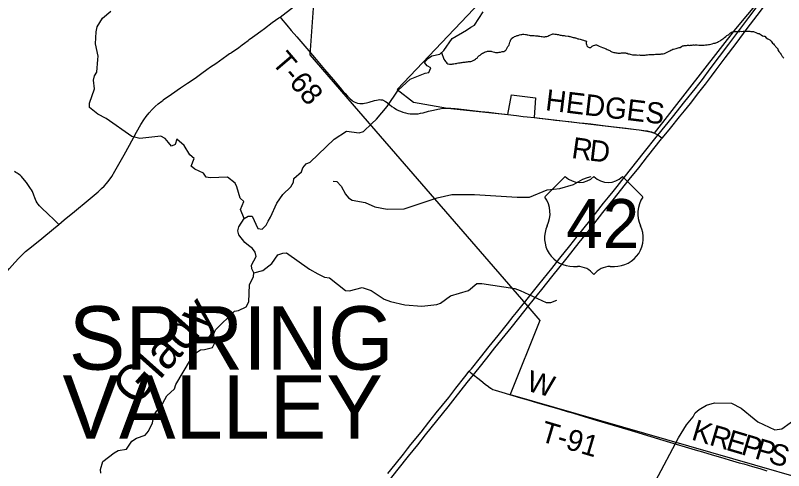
# Model space of a CAD drawing. Extents: x -19.5 to 44.1, y 0 to 22.
# Drawn here: x -15.579 to -13.513, y 18.108 to 19.332 of the extents above; entities that cross this region are included whole.
import ezdxf

# ---------------------------------------------------------------- set-up
doc = ezdxf.new("R2010")
doc.units = 0
for name, color, linetype in [('GM_X_Corporation', 7, 'Continuous'), ('GM_X_County_Road', 7, 'Continuous'), ('GM_X_Minor_River', 7, 'Continuous'), ('GM_X_Minor_River_Text', 7, 'Continuous'), ('GM_X_Township', 7, 'Continuous'), ('GM_X_Township_Road', 7, 'Continuous'), ('GM_X_Township_Road_Text', 7, 'Continuous'), ('GM_X_Township_Text', 7, 'Continuous'), ('GM_X_US_Location', 7, 'Continuous'), ('GM_X_US_Route', 7, 'Continuous'), ('GM_X_US_Shield', 7, 'Continuous')]:
    doc.layers.add(name, color=color, linetype=linetype)

msp = doc.modelspace()

# ---------------------------------------------------------------- linework, layer by layer
at = {"layer": 'GM_X_Corporation'}
msp.add_lwpolyline([(-14.0734, 19.638), (-14.5525, 19.1324), (-14.5085, 19.0988), (-14.4176, 19.0831), (-14.2547, 19.0654), (-14.2455, 19.1182), (-14.1803, 19.1107), (-14.1842, 19.0573), (-13.9021, 19.0241), (-13.8716, 19.0193), (-13.8606, 19.0152), (-13.6422, 19.296), (-13.5447, 19.4122)], dxfattribs=at)
at = {"layer": 'GM_X_County_Road'}
for points in [[(-14.8675, 19.3277), (-14.8315, 19.3546)], [(-15.4629, 18.7701), (-15.4479, 18.7823), (-15.4207, 18.805), (-15.384, 18.8357), (-15.3571, 18.8578), (-15.3474, 18.8665), (-15.3404, 18.8734), (-15.3342, 18.8803), (-15.3273, 18.889), (-15.3203, 18.8992), (-15.3119, 18.9129), (-15.2975, 18.9383), (-15.287, 18.9573), (-15.2726, 18.9834), (-15.2534, 19.0182), (-15.2418, 19.0388), (-15.2343, 19.051), (-15.2279, 19.0602), (-15.2197, 19.0704), (-15.2117, 19.0792), (-15.2033, 19.0875), (-15.1952, 19.0944), (-15.1859, 19.1016), (-15.183, 19.1037), (-15.1816, 19.1047), (-15.1592, 19.1203), (-15.1353, 19.137), (-15.1169, 19.1497), (-15.0962, 19.1635), (-15.0775, 19.1768), (-15.0644, 19.1863), (-15.0543, 19.1934), (-15.0406, 19.2029), (-15.0103, 19.2246), (-15.0032, 19.2295), (-15.0011, 19.2308), (-14.9986, 19.2326), (-14.9945, 19.2353), (-14.9903, 19.2379), (-14.9787, 19.2461), (-14.9691, 19.253), (-14.9636, 19.257), (-14.9535, 19.2645), (-14.9502, 19.2669), (-14.9418, 19.2731), (-14.9353, 19.278), (-14.9193, 19.2896), (-14.9094, 19.297), (-14.8884, 19.3126), (-14.8707, 19.3252), (-14.8675, 19.3277)], [(-15.7973, 18.403), (-15.7928, 18.4083), (-15.7779, 18.4266), (-15.7621, 18.4466), (-15.7433, 18.4706), (-15.7194, 18.5016), (-15.7037, 18.5216), (-15.692, 18.5362), (-15.6732, 18.5593), (-15.6533, 18.5832), (-15.6076, 18.6373), (-15.5955, 18.6515), (-15.5813, 18.6679), (-15.5704, 18.6799), (-15.5615, 18.6887), (-15.5522, 18.697), (-15.5364, 18.71), (-15.5083, 18.7326), (-15.4767, 18.7587), (-15.4629, 18.7701)]]:
    msp.add_lwpolyline(points, dxfattribs=at)
at = {"layer": 'GM_X_Minor_River'}
for points in [[(-14.9644, 18.7865), (-14.9739, 18.8102), (-14.9651, 18.832), (-14.9749, 18.8406), (-14.9834, 18.8715), (-14.9886, 18.8811), (-15.0088, 18.8973), (-15.0552, 18.8951), (-15.0661, 18.8976), (-15.0739, 18.908), (-15.0969, 18.9186), (-15.107, 18.9267), (-15.0987, 18.9475), (-15.1099, 18.9576), (-15.1258, 18.9821), (-15.1449, 18.9995), (-15.1493, 18.9848), (-15.1597, 18.9804), (-15.1675, 18.9901), (-15.1768, 19.0012), (-15.1881, 19.0071), (-15.2447, 19.0009), (-15.2663, 19.0062), (-15.3349, 19.0552), (-15.3579, 19.0666), (-15.3804, 19.0848), (-15.3802, 19.0959), (-15.367, 19.1347), (-15.3692, 19.1583), (-15.3668, 19.1697), (-15.3605, 19.1794), (-15.3577, 19.2132), (-15.3571, 19.2227), (-15.3638, 19.2558), (-15.3625, 19.2877), (-15.3596, 19.3013), (-15.3448, 19.3242), (-15.3228, 19.3432)], [(-14.7219, 18.9991), (-14.6893, 19.0206), (-14.6552, 19.0162), (-14.6434, 19.0198), (-14.621, 19.0415), (-14.6079, 19.053), (-14.5792, 19.0871), (-14.5503, 19.131), (-14.5175, 19.1608), (-14.477, 19.1768), (-14.4671, 19.1782), (-14.462, 19.191), (-14.4721, 19.1961), (-14.4792, 19.2057), (-14.4714, 19.2155), (-14.4592, 19.2229), (-14.4378, 19.2274), (-14.427, 19.2379), (-14.4044, 19.2701), (-14.3665, 19.2927), (-14.3546, 19.3001), (-14.345, 19.306), (-14.3212, 19.342)], [(-14.4331, 19.2322), (-14.4271, 19.2144), (-14.4245, 19.2109), (-14.4222, 19.2079), (-14.4211, 19.206), (-14.4188, 19.2033), (-14.4166, 19.2021), (-14.4116, 19.201), (-14.4094, 19.2013), (-14.4075, 19.2013), (-14.4048, 19.2013), (-14.4029, 19.2016), (-14.3999, 19.202), (-14.3968, 19.2027), (-14.3931, 19.2031), (-14.3912, 19.2034), (-14.3874, 19.2042), (-14.3847, 19.2045), (-14.3828, 19.2045), (-14.3801, 19.2052), (-14.3775, 19.2056), (-14.3748, 19.206), (-14.3726, 19.2063), (-14.3695, 19.2067), (-14.3672, 19.207), (-14.365, 19.207), (-14.3631, 19.2074), (-14.3608, 19.2077), (-14.3585, 19.2077), (-14.3566, 19.2081), (-14.3547, 19.2084), (-14.3521, 19.2088), (-14.3486, 19.2107), (-14.3464, 19.2118), (-14.3445, 19.2129), (-14.3422, 19.2148), (-14.3399, 19.2163), (-14.3372, 19.2174), (-14.3357, 19.2204), (-14.3326, 19.2234), (-14.3296, 19.2253), (-14.328, 19.2272), (-14.3254, 19.2291), (-14.3227, 19.2306), (-14.3208, 19.2313), (-14.3178, 19.2332), (-14.3151, 19.2339), (-14.3117, 19.235), (-14.3098, 19.2358), (-14.3079, 19.2357), (-14.306, 19.2357), (-14.303, 19.2357), (-14.2999, 19.2357), (-14.2977, 19.2353), (-14.2946, 19.2345), (-14.2912, 19.2333), (-14.2882, 19.2325), (-14.2848, 19.2321), (-14.2829, 19.2321), (-14.2806, 19.2325), (-14.278, 19.2328), (-14.2749, 19.2336), (-14.27, 19.2347), (-14.2673, 19.235), (-14.2654, 19.2354), (-14.2635, 19.2369), (-14.2616, 19.238), (-14.2597, 19.2391), (-14.257, 19.2444), (-14.2547, 19.2482), (-14.2524, 19.2512), (-14.2513, 19.2531), (-14.2509, 19.2561), (-14.2493, 19.2599), (-14.2482, 19.2633), (-14.2474, 19.2652), (-14.2459, 19.2671), (-14.2447, 19.2697), (-14.2413, 19.2727), (-14.2386, 19.2738), (-14.2367, 19.2753), (-14.2336, 19.2765), (-14.2298, 19.2779), (-14.2268, 19.2783), (-14.2234, 19.2798), (-14.22, 19.2805), (-14.2173, 19.2809), (-14.2147, 19.2812), (-14.2116, 19.2812), (-14.2078, 19.2804), (-14.2056, 19.2804), (-14.2033, 19.28), (-14.201, 19.2796), (-14.1972, 19.2788), (-14.1953, 19.2784), (-14.1931, 19.278), (-14.1885, 19.278), (-14.1859, 19.2776), (-14.184, 19.2776), (-14.1806, 19.2771)], [(-14.1806, 19.2771), (-14.1783, 19.2767), (-14.1764, 19.2767), (-14.1745, 19.2767), (-14.1726, 19.2763), (-14.1703, 19.2763), (-14.1685, 19.2759), (-14.1654, 19.2755), (-14.1628, 19.2751), (-14.1594, 19.2747), (-14.1575, 19.2747), (-14.1556, 19.2746), (-14.1533, 19.275), (-14.1499, 19.2757), (-14.1476, 19.2765), (-14.1446, 19.278), (-14.1419, 19.2791), (-14.14, 19.2794), (-14.1362, 19.2817), (-14.1339, 19.2821), (-14.132, 19.2824), (-14.129, 19.282), (-14.1271, 19.2816), (-14.1252, 19.2812), (-14.1226, 19.2808), (-14.1191, 19.2804), (-14.1165, 19.2796), (-14.1142, 19.2792), (-14.1116, 19.2788), (-14.1085, 19.2784), (-14.1063, 19.278), (-14.1036, 19.2776), (-14.1006, 19.2772), (-14.093, 19.276), (-14.0911, 19.276), (-14.0892, 19.2756), (-14.087, 19.2752), (-14.0847, 19.2744), (-14.0821, 19.2736), (-14.0794, 19.2728), (-14.0768, 19.2724), (-14.0749, 19.2721), (-14.073, 19.2713), (-14.0703, 19.2705), (-14.0684, 19.2701), (-14.0665, 19.2693), (-14.0643, 19.2689), (-14.0609, 19.2681), (-14.0575, 19.2673), (-14.0548, 19.2662), (-14.0518, 19.2658), (-14.0495, 19.2646), (-14.0465, 19.2635), (-14.0435, 19.2623), (-14.0446, 19.26), (-14.0447, 19.2566), (-14.0436, 19.2539), (-14.0421, 19.2501), (-14.0402, 19.2475), (-14.036, 19.2459), (-14.0341, 19.2459), (-14.0322, 19.2459), (-14.0303, 19.2474), (-14.0281, 19.2489), (-14.0261, 19.2504), (-14.0242, 19.2515), (-14.0212, 19.2522), (-14.0185, 19.2526), (-14.0163, 19.2526), (-14.0129, 19.251), (-14.0091, 19.2495), (-14.0049, 19.2475), (-14.0008, 19.246), (-13.9978, 19.2444), (-13.9951, 19.244), (-13.9932, 19.2433), (-13.9902, 19.2417), (-13.9876, 19.2406), (-13.9811, 19.2378), (-13.9793, 19.2363), (-13.977, 19.2352), (-13.9751, 19.2344), (-13.9725, 19.2336), (-13.9702, 19.2324), (-13.9675, 19.232), (-13.9649, 19.2316), (-13.9622, 19.2312), (-13.9592, 19.2304), (-13.9566, 19.2304), (-13.9543, 19.2304), (-13.9516, 19.2304), (-13.9494, 19.2311), (-13.9467, 19.2311), (-13.9437, 19.2311), (-13.941, 19.231), (-13.9387, 19.231), (-13.9369, 19.2306), (-13.9342, 19.2302), (-13.9319, 19.2291), (-13.9285, 19.2283), (-13.9259, 19.2275)], [(-13.9259, 19.2275), (-13.9195, 19.2259), (-13.916, 19.2259), (-13.913, 19.2259), (-13.9111, 19.2259), (-13.9092, 19.2258), (-13.9051, 19.2254), (-13.902, 19.2258), (-13.899, 19.2254), (-13.8952, 19.2253), (-13.8922, 19.2253), (-13.8903, 19.2253), (-13.888, 19.2253), (-13.8857, 19.2253), (-13.8831, 19.226), (-13.8797, 19.2263), (-13.8762, 19.2267), (-13.8724, 19.2267), (-13.8698, 19.2266), (-13.8671, 19.2266), (-13.8645, 19.2266), (-13.8611, 19.2269), (-13.858, 19.2277), (-13.8561, 19.2277), (-13.8542, 19.2276), (-13.8512, 19.2276), (-13.8478, 19.2276), (-13.8448, 19.2279), (-13.8429, 19.2283), (-13.8402, 19.2283), (-13.8372, 19.229), (-13.8338, 19.2297), (-13.8319, 19.2305), (-13.825, 19.2342), (-13.8231, 19.235), (-13.8193, 19.2372), (-13.8166, 19.2387), (-13.814, 19.2398), (-13.8109, 19.2409), (-13.809, 19.2413), (-13.806, 19.2424), (-13.8022, 19.2431), (-13.7999, 19.2439), (-13.7969, 19.2446), (-13.7946, 19.2453), (-13.7919, 19.2457), (-13.7877, 19.2483), (-13.7851, 19.2498), (-13.7824, 19.2502), (-13.7805, 19.2509), (-13.7779, 19.2509), (-13.7741, 19.2512), (-13.7718, 19.2516), (-13.7691, 19.2516), (-13.7661, 19.2515), (-13.7642, 19.2519), (-13.7616, 19.2523), (-13.7593, 19.2522), (-13.7566, 19.2526), (-13.7547, 19.2526), (-13.7528, 19.2522), (-13.7506, 19.2525), (-13.7479, 19.2525), (-13.7456, 19.2525), (-13.7411, 19.2521), (-13.7392, 19.2521), (-13.7358, 19.252), (-13.732, 19.252), (-13.7301, 19.2524), (-13.7271, 19.2523), (-13.7233, 19.2527), (-13.7191, 19.253), (-13.7153, 19.2538), (-13.713, 19.2537), (-13.7092, 19.2548), (-13.7054, 19.2559), (-13.7009, 19.2574), (-13.6975, 19.2578), (-13.6952, 19.2585), (-13.6929, 19.2596), (-13.691, 19.26), (-13.688, 19.2615), (-13.6841, 19.2637), (-13.6822, 19.2656), (-13.6792, 19.2675), (-13.6769, 19.2686), (-13.6746, 19.2701), (-13.6727, 19.2727), (-13.6689, 19.2754), (-13.6658, 19.2776), (-13.6639, 19.2787), (-13.6617, 19.2799), (-13.6586, 19.2829), (-13.6559, 19.2847), (-13.6533, 19.2866), (-13.6506, 19.2881), (-13.6479, 19.2885), (-13.6445, 19.2884), (-13.6419, 19.2888), (-13.64, 19.2884), (-13.6369, 19.2884)], [(-13.6369, 19.2884), (-13.6339, 19.2891), (-13.6313, 19.2891), (-13.629, 19.2894), (-13.6263, 19.289), (-13.6218, 19.2894), (-13.6161, 19.2893), (-13.6115, 19.2897), (-13.6081, 19.2896), (-13.6043, 19.2892), (-13.6017, 19.2888), (-13.5979, 19.2884), (-13.5945, 19.2884), (-13.5866, 19.2849), (-13.5828, 19.2837), (-13.5794, 19.2833), (-13.5741, 19.2799), (-13.5699, 19.2775), (-13.5662, 19.2764), (-13.5639, 19.276), (-13.5598, 19.2718), (-13.5556, 19.2691), (-13.5526, 19.2671), (-13.5507, 19.2664), (-13.5484, 19.2645), (-13.5469, 19.2625), (-13.5447, 19.2602), (-13.5428, 19.2576), (-13.5402, 19.2553), (-13.5383, 19.2526), (-13.5364, 19.2503), (-13.5349, 19.2484), (-13.5334, 19.2465), (-13.5315, 19.2446), (-13.5289, 19.2419), (-13.5289, 19.2392), (-13.5263, 19.2354), (-13.5237, 19.2327), (-13.5226, 19.2305), (-13.5203, 19.2266), (-13.5181, 19.2236), (-13.5162, 19.2213), (-13.5151, 19.2194), (-13.5128, 19.2171)], [(-15.3493, 18.102), (-15.3503, 18.1115), (-15.3446, 18.1326), (-15.3138, 18.156), (-15.3031, 18.1627), (-15.2806, 18.1665), (-15.2666, 18.1879), (-15.2536, 18.196), (-15.2306, 18.2036), (-15.221, 18.2144), (-15.2103, 18.2367), (-15.2062, 18.2582), (-15.1991, 18.2691), (-15.1891, 18.2777), (-15.1723, 18.3097), (-15.1518, 18.3279), (-15.1478, 18.34), (-15.108, 18.4058), (-15.092, 18.426), (-15.0813, 18.433), (-15.071, 18.4344), (-15.0497, 18.4397), (-15.0438, 18.4499), (-15.0456, 18.4761), (-15.0409, 18.4866), (-14.9903, 18.5374), (-14.9793, 18.5384), (-14.959, 18.5483), (-14.9511, 18.5618), (-14.95, 18.6077), (-14.9393, 18.63), (-14.938, 18.6402), (-14.9439, 18.6509), (-14.9445, 18.6608), (-14.9316, 18.6838), (-14.9341, 18.6952), (-14.9415, 18.7056), (-14.952, 18.7133), (-14.9621, 18.7219), (-14.9788, 18.7423), (-14.9809, 18.7526), (-14.9781, 18.7635), (-14.9644, 18.7865), (-14.9533, 18.7923), (-14.9426, 18.7922), (-14.9269, 18.7589), (-14.9159, 18.7575), (-14.9051, 18.768), (-14.8992, 18.7793), (-14.893, 18.7894), (-14.876, 18.8271), (-14.8604, 18.8508), (-14.8388, 18.8716), (-14.8317, 18.8837), (-14.8308, 18.8939), (-14.8096, 18.9114), (-14.806, 18.9227), (-14.7971, 18.9328), (-14.7864, 18.9372), (-14.7219, 18.9991)], [(-14.725, 18.8864), (-14.7148, 18.8855), (-14.7036, 18.8731), (-14.6914, 18.8513), (-14.6832, 18.8416), (-14.6735, 18.8358), (-14.6386, 18.8287), (-14.613, 18.8177), (-14.5797, 18.811), (-14.5338, 18.8125), (-14.4448, 18.8417), (-14.4055, 18.8509), (-14.3444, 18.8506), (-14.2302, 18.8434), (-14.1964, 18.8436), (-14.149, 18.8632), (-14.1148, 18.8665), (-14.0785, 18.8776), (-14.0532, 18.8916), (-14.0406, 18.8959), (-14.0307, 18.8988)], [(-14.938, 18.6402), (-14.9136, 18.6462), (-14.8898, 18.6648), (-14.8738, 18.6881), (-14.86, 18.6932), (-14.8502, 18.6934), (-14.7886, 18.6498), (-14.7661, 18.6372), (-14.7476, 18.6286), (-14.7344, 18.6268), (-14.6913, 18.5923), (-14.6811, 18.5914), (-14.6467, 18.601), (-14.6229, 18.593), (-14.5873, 18.5689), (-14.5707, 18.5629), (-14.5321, 18.5539), (-14.4862, 18.5508), (-14.4459, 18.5547), (-14.436, 18.5587), (-14.409, 18.578), (-14.361, 18.5927), (-14.3386, 18.6113), (-14.3246, 18.6118), (-14.2363, 18.5982), (-14.222, 18.593), (-14.1519, 18.5603), (-14.1394, 18.5604), (-14.123, 18.5662)], [(-13.8575, 18.0802), (-13.7959, 18.1965), (-13.7744, 18.2318), (-13.7566, 18.2531), (-13.7515, 18.2633), (-13.7403, 18.273), (-13.7204, 18.284), (-13.699, 18.2905), (-13.6538, 18.2897), (-13.6271, 18.2767), (-13.5926, 18.2477), (-13.5829, 18.2391), (-13.5373, 18.2178), (-13.5179, 18.2209), (-13.4737, 18.2532)]]:
    msp.add_lwpolyline(points, dxfattribs=at)
at = {"layer": 'GM_X_Township'}
msp.add_lwpolyline([(-14.6681, 20.8984), (-14.6789, 20.7469), (-14.7755, 19.39), (-14.7872, 19.2258), (-14.6567, 19.0745), (-14.2066, 18.556), (-14.1687, 18.5123), (-14.2489, 18.3126), (-13.2894, 18.0374), (-13.0816, 17.9779), (-12.8625, 17.915), (-12.8577, 17.9033), (-12.8422, 17.8924), (-12.6248, 17.8299), (-12.4862, 17.7901), (-12.413, 17.7691)], dxfattribs=at)
at = {"layer": 'GM_X_Township_Road'}
for points in [[(-14.8675, 19.3277), (-14.8643, 19.3237), (-14.8496, 19.3058), (-14.8375, 19.2916)], [(-14.8375, 19.2916), (-14.8228, 19.2743), (-14.7959, 19.2429), (-14.7708, 19.2135), (-14.7477, 19.1866), (-14.7248, 19.1596), (-14.7012, 19.132), (-14.6925, 19.1219), (-14.6865, 19.115), (-14.6827, 19.111), (-14.6781, 19.1066), (-14.6748, 19.1039), (-14.673, 19.1027)], [(-14.673, 19.1027), (-14.6719, 19.1019), (-14.6683, 19.0998), (-14.6642, 19.0981), (-14.659, 19.0965), (-14.6531, 19.0954), (-14.6483, 19.0952), (-14.6441, 19.0952), (-14.6401, 19.0957), (-14.6352, 19.097), (-14.6281, 19.099), (-14.6137, 19.1033), (-14.6083, 19.1046), (-14.604, 19.1054), (-14.6001, 19.1056), (-14.5963, 19.1055), (-14.5923, 19.1047), (-14.5881, 19.1029), (-14.5872, 19.1024)], [(-14.5872, 19.1024), (-14.5839, 19.1005), (-14.5797, 19.0975), (-14.5668, 19.0875), (-14.5609, 19.0835), (-14.5543, 19.0794), (-14.5491, 19.0766), (-14.5436, 19.0743), (-14.5375, 19.0719), (-14.5306, 19.07), (-14.5241, 19.0687), (-14.5174, 19.0677), (-14.5105, 19.0672), (-14.5031, 19.0674), (-14.496, 19.0678), (-14.4897, 19.0688), (-14.4823, 19.0703), (-14.4682, 19.0742), (-14.4549, 19.0776), (-14.4434, 19.0803), (-14.4383, 19.0813), (-14.4302, 19.0823), (-14.4241, 19.0828), (-14.4176, 19.0831)], [(-14.4176, 19.0831), (-14.408, 19.0829), (-14.3968, 19.0819), (-14.3876, 19.0808), (-14.3272, 19.0738), (-14.3057, 19.0716), (-14.2792, 19.0684), (-14.2619, 19.0663), (-14.2547, 19.0654)], [(-14.2547, 19.0654), (-14.2318, 19.0628), (-14.2139, 19.0607), (-14.2028, 19.0594), (-14.1842, 19.0573)], [(-14.1842, 19.0573), (-14.1711, 19.0559), (-14.1389, 19.0524), (-14.1266, 19.0508), (-14.1081, 19.0487), (-14.0828, 19.0459), (-14.0631, 19.0434), (-14.0501, 19.042), (-14.0322, 19.0401), (-13.9927, 19.0352), (-13.9606, 19.0314), (-13.9366, 19.0285), (-13.9101, 19.0251), (-13.9021, 19.0241), (-13.8891, 19.0226), (-13.8804, 19.0213), (-13.8743, 19.0201), (-13.8688, 19.0186), (-13.8641, 19.0169), (-13.8606, 19.0152), (-13.8538, 19.0115), (-13.8514, 19.0101)], [(-13.8514, 19.0101), (-13.8492, 19.0088), (-13.8431, 19.0051), (-13.8394, 19.0027)], [(-15.4629, 18.7701), (-15.4677, 18.7752), (-15.4686, 18.7762), (-15.4761, 18.7836), (-15.4914, 18.7978), (-15.5093, 18.8147), (-15.5144, 18.8203), (-15.5178, 18.8244), (-15.5208, 18.8285), (-15.5231, 18.833), (-15.5249, 18.8372), (-15.5268, 18.8414), (-15.53, 18.8492), (-15.5337, 18.8586), (-15.5357, 18.8629), (-15.5386, 18.8669), (-15.542, 18.8719), (-15.5459, 18.8773), (-15.5495, 18.8825), (-15.5545, 18.8888), (-15.5626, 18.8986), (-15.5658, 18.9013), (-15.5681, 18.9032), (-15.5717, 18.906), (-15.575, 18.9082), (-15.5784, 18.91), (-15.5819, 18.9121)], [(-14.3586, 18.3754), (-14.356, 18.3734), (-14.3471, 18.3663)], [(-14.3471, 18.3663), (-14.3353, 18.3571), (-14.3278, 18.3509), (-14.316, 18.3408), (-14.3072, 18.3341), (-14.3014, 18.3303)], [(-14.3014, 18.3303), (-14.3005, 18.3297), (-14.2951, 18.3269), (-14.2888, 18.3246), (-14.2709, 18.3194), (-14.2207, 18.3043), (-14.2112, 18.3017), (-14.1988, 18.2979), (-14.1748, 18.291), (-14.1623, 18.2874), (-14.1498, 18.2838), (-14.1403, 18.2809), (-14.1242, 18.276), (-14.1153, 18.2732), (-14.0951, 18.2674), (-14.0814, 18.2635), (-14.0612, 18.2574), (-14.0178, 18.2443), (-13.9562, 18.2258), (-13.9142, 18.2134), (-13.8701, 18.2002), (-13.8382, 18.1905), (-13.8019, 18.1798), (-13.7781, 18.1727), (-13.7515, 18.1645), (-13.7312, 18.1586), (-13.7054, 18.1509), (-13.6829, 18.1442), (-13.6599, 18.1377), (-13.6325, 18.1297), (-13.6205, 18.1263), (-13.5966, 18.1192), (-13.5774, 18.1137), (-13.5586, 18.1082)]]:
    msp.add_lwpolyline(points, dxfattribs=at)
at = {"layer": 'GM_X_US_Route'}
for points in [[(-13.8413, 19.0003), (-13.8394, 19.0027), (-13.8176, 19.0289), (-13.793, 19.0594), (-13.7801, 19.0753), (-13.7641, 19.0951), (-13.741, 19.1244), (-13.7233, 19.1476), (-13.7076, 19.1684), (-13.6946, 19.1859), (-13.6815, 19.2032), (-13.6703, 19.2181), (-13.6412, 19.2569), (-13.6109, 19.2971), (-13.5847, 19.3318), (-13.5478, 19.381), (-13.5254, 19.4109), (-13.5049, 19.4382)], [(-14.5774, 18.1004), (-14.5578, 18.1253), (-14.5357, 18.153), (-14.5248, 18.1666), (-14.5155, 18.1782), (-14.4883, 18.2122), (-14.4676, 18.2385), (-14.4474, 18.2638), (-14.4139, 18.3054), (-14.3946, 18.3298), (-14.3708, 18.3601), (-14.3586, 18.3754), (-14.353, 18.3824), (-14.3289, 18.4125), (-14.3053, 18.4421), (-14.2814, 18.4716), (-14.2562, 18.503), (-14.2405, 18.5224), (-14.2315, 18.5335), (-14.2174, 18.5511), (-14.2094, 18.5612), (-14.1932, 18.5816), (-14.1714, 18.6087), (-14.1367, 18.6518), (-14.1151, 18.6791), (-14.0883, 18.7125), (-14.0685, 18.7374), (-14.0349, 18.7797), (-13.9973, 18.8276), (-13.9844, 18.8435), (-13.9718, 18.8589), (-13.961, 18.8725), (-13.9421, 18.8964), (-13.9215, 18.9221), (-13.9079, 18.939), (-13.887, 18.9653), (-13.8559, 19.0043), (-13.8514, 19.0101), (-13.8124, 19.0581), (-13.7786, 19.1003), (-13.7511, 19.1348), (-13.7317, 19.1599), (-13.7105, 19.1883), (-13.6609, 19.2544), (-13.634, 19.2902), (-13.6068, 19.3265), (-13.5847, 19.3557)], [(-13.8793, 18.9526), (-13.8413, 19.0003)], [(-14.5832, 18.0702), (-14.5497, 18.1119), (-14.5217, 18.1475), (-14.4973, 18.1781), (-14.4762, 18.2042), (-14.4159, 18.2802), (-14.3968, 18.3038), (-14.3645, 18.3449), (-14.3471, 18.3663), (-14.3402, 18.3747), (-14.3321, 18.3849), (-14.3117, 18.4108), (-14.2896, 18.4385), (-14.254, 18.4824), (-14.2459, 18.4925), (-14.2256, 18.5178), (-14.1981, 18.5523), (-14.1639, 18.595), (-14.1363, 18.6294), (-14.0957, 18.6805), (-14.0629, 18.7218), (-14.0393, 18.7515), (-13.9991, 18.8021), (-13.9716, 18.8366), (-13.9285, 18.8905), (-13.9031, 18.9227), (-13.8793, 18.9526)]]:
    msp.add_lwpolyline(points, dxfattribs=at)
at = {"layer": 'GM_X_US_Shield'}
for p, q in [((-14.1004, 18.8988), (-14.1554, 18.8439)), ((-13.8917, 18.8439), (-13.9466, 18.8988)), ((-14.0785, 18.6571), (-14.0675, 18.6571)), ((-13.9796, 18.6571), (-13.9686, 18.6571))]:
    msp.add_line(p, q, dxfattribs=at)
for centre, radius, start, end in [((-14.062, 18.938), 0.0549, 225.573, 314.427), ((-13.9851, 18.938), 0.0549, 225.573, 314.427), ((-14.2184, 18.7997), 0.0769, 334.5471, 35.0009), ((-13.8287, 18.7997), 0.0769, 144.9991, 205.4529), ((-14.0793, 18.734), 0.0769, 154.8319, 270.6383), ((-13.9677, 18.734), 0.0769, 269.3617, 25.1681), ((-14.0675, 18.6022), 0.0549, 36.8699, 90), ((-13.9796, 18.6022), 0.0549, 90, 143.1301)]:
    msp.add_arc(centre, radius, start, end, dxfattribs=at)

# ---------------------------------------------------------------- texts
at = {"layer": 'GM_X_Minor_River_Text'}
msp.add_text('Glady', height=0.09469, rotation=48.2616, dxfattribs=at).set_placement((-15.2566, 18.2775))
at = {"layer": 'GM_X_Township_Road_Text'}
for s, height, rotation, p in [('T-68', 0.05682, 310.4897, (-14.8921, 19.2048)), ('HEDGES', 0.05682, 353.1096, (-14.1558, 19.0774)), ('R', 0.0568, 351.8782, (-14.0856, 18.949)), ('D', 0.0568, 353.2021, (-14.038, 18.9422)), ('W', 0.0568, 344.5585, (-14.2081, 18.3242)), ('K', 0.0568, 343.4511, (-13.7638, 18.1925)), ('T-91', 0.05682, 343.4106, (-14.171, 18.1884)), ('R', 0.0568, 343.4514, (-13.7158, 18.1783)), ('E', 0.0568, 343.4506, (-13.6711, 18.165)), ('P', 0.0568, 343.4502, (-13.6304, 18.1529)), ('P', 0.0568, 343.445, (-13.5936, 18.1419)), ('S', 0.0568, 342.9836, (-13.557, 18.1311))]:
    msp.add_text(s, height=height, rotation=rotation, dxfattribs=at).set_placement(p)
at = {"layer": 'GM_X_Township_Text'}
for s, p in [('SPRING', (-15.4356, 18.3798)), ('VALLEY', (-15.4527, 18.1942))]:
    msp.add_text(s, height=0.17045, rotation=0, dxfattribs=at).set_placement(p)
at = {"layer": 'GM_X_US_Location'}
for s in ['0', '/']:
    msp.add_text(s, height=0.000189, dxfattribs=at).set_placement((-14.0236, 18.7714))
msp.add_text('42', height=0.000189, rotation=0, dxfattribs=at).set_placement((-14.0627, 18.7322))
at = {"layer": 'GM_X_US_Shield'}
msp.add_text('42', height=0.13184, dxfattribs=at).set_placement((-14.0977, 18.7065))

doc.saveas('drawing.dxf')
